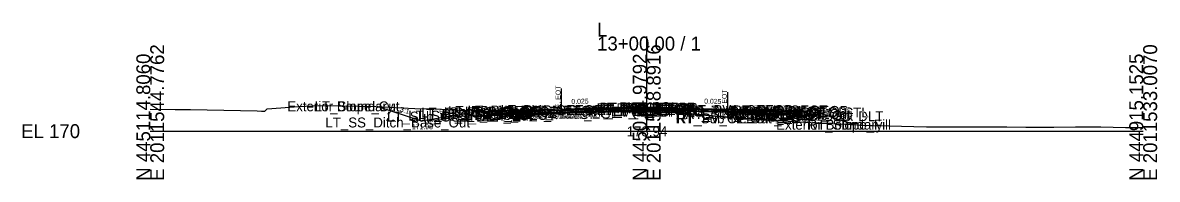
# Model space of a CAD drawing. Extents: x -26 to 4203, y -10 to 9526.
# Drawn here: x -25.7 to 202.8, y 2990.3 to 3021.8 of the extents above; entities that cross this region are included whole.
import ezdxf

# ---------------------------------------------------------------- set-up
doc = ezdxf.new("R2010")
doc.units = 0
for name, color, linetype in [('Default', 7, 'Continuous'), ('Exist CMT Pavement', 7, 'Continuous'), ('Exist Cross Section Cell', 7, 'Continuous'), ('Exist XS Center Line Elevation Label', 7, 'Continuous'), ('Exist XS Ground Line', 7, 'Continuous'), ('Prop CMT Pvmt Course 1', 7, 'Continuous'), ('Prop CMT Pvmt Course 1 Wedge', 7, 'Continuous'), ('Prop CMT Pvmt Course 2', 7, 'Continuous'), ('Prop CMT Pvmt Course 2 Wedge', 7, 'Continuous'), ('Prop CMT Pvmt Course 3', 7, 'Continuous'), ('Prop CMT Pvmt Course 3 Wedge', 7, 'Continuous'), ('Prop CMT Pvmt Surface', 7, 'Continuous'), ('Prop CMT Pvmt Surface Shoulder', 7, 'Continuous'), ('Prop CMT Pvmt Wedge Surface 1', 7, 'Continuous'), ('Prop CMT Pvmt Wedge Surface 2', 7, 'Continuous'), ('Prop CMT Pvmt Wedge Surface 3', 7, 'Continuous'), ('Prop CMT Shld Paved Course 1', 7, 'Continuous'), ('Prop CMT Shld Paved Course 2', 7, 'Continuous'), ('Prop CMT Shld Paved Course 3', 7, 'Continuous'), ('Prop CMT Slope Grass', 7, 'Continuous'), ('Prop CMT Subgrade Earthwork', 7, 'Continuous'), ('Prop XS Ditch Standard Text', 7, 'Continuous'), ('Prop XS Label Text', 7, 'Continuous'), ('Prop XS SE Text', 7, 'Continuous'), ('Prop XS Side Slope Text', 7, 'Continuous'), ('Scratch_Level_0', 7, 'Continuous')]:
    doc.layers.add(name, color=color, linetype=linetype)

msp = doc.modelspace()

# ---------------------------------------------------------------- linework, layer by layer
at = {"layer": 'Exist CMT Pavement'}
for points in [[(80.68, 3003.54), (81.66, 3003.57), (82.5, 3003.6), (82.74, 3003.61), (84.46, 3003.66), (84.88, 3003.67), (85.13, 3003.68), (87.41, 3003.75), (89.36, 3003.83), (89.86, 3003.85), (89.9, 3003.85), (92.24, 3003.89), (92.41, 3003.9), (92.53, 3003.9), (93.92, 3003.95), (94.77, 3003.96), (94.93, 3003.96), (96.98, 3003.96), (97.42, 3003.96), (99.36, 3003.95), (99.94, 3003.94), (100, 3003.94)], [(100, 3003.94), (100.59, 3003.91), (102.41, 3003.84), (104.06, 3003.77), (104.99, 3003.73), (105.05, 3003.73), (105.75, 3003.68), (107.43, 3003.55), (108.77, 3003.47), (109.9, 3003.39), (111.2, 3003.27), (112.43, 3003.15), (113.87, 3003.04), (114.93, 3002.96), (116.13, 3002.83), (116.24, 3002.82), (116.37, 3002.81), (117.45, 3002.67), (118.16, 3002.62), (118.55, 3002.57)]]:
    msp.add_lwpolyline(points, dxfattribs=at)
at = {"layer": 'Exist Cross Section Cell'}
for p, q in [((100, 3000), (100, 3019.03)), ((0, 3000), (100, 3000)), ((100, 3000), (200, 3000))]:
    msp.add_line(p, q, dxfattribs=at)
at = {"layer": 'Exist XS Ground Line'}
msp.add_lwpolyline([(0, 3004.45), (5.03, 3004.38), (8.14, 3004.34), (21.53, 3004.11), (22.4, 3004.05), (23.11, 3004.01), (23.53, 3004.51), (29.96, 3004.98), (33.94, 3005.14), (38.11, 3005.07), (45.41, 3004.96), (53.32, 3004.56), (57.33, 3004.49), (65.33, 3004.11), (65.98, 3004.11), (66.59, 3004.11), (67.2, 3004.09), (71.19, 3003.93), (76.37, 3003.67), (77.31, 3003.66), (78.95, 3003.6), (80.68, 3003.54), (81.66, 3003.57), (82.74, 3003.61), (84.46, 3003.66), (85.13, 3003.68), (87.41, 3003.75), (89.36, 3003.83), (89.9, 3003.85), (92.53, 3003.9), (93.92, 3003.95), (94.93, 3003.96), (96.98, 3003.96), (97.42, 3003.96), (99.36, 3003.95), (100, 3003.94), (100.59, 3003.91), (102.41, 3003.84), (104.06, 3003.77), (105.05, 3003.73), (105.75, 3003.68), (107.43, 3003.55), (108.77, 3003.47), (109.9, 3003.39), (111.2, 3003.27), (112.43, 3003.15), (113.87, 3003.04), (114.93, 3002.96), (116.24, 3002.82), (117.45, 3002.67), (118.16, 3002.62), (118.55, 3002.57), (125.06, 3002.24), (134.2, 3001.69), (134.8, 3001.65), (135.25, 3001.63), (135.81, 3001.6), (136.29, 3001.59), (144.77, 3001.15), (145.57, 3001.14), (148.75, 3001.07), (156.33, 3000.9), (163.07, 3000.85), (166.35, 3000.86), (172.53, 3000.84), (176.37, 3000.78), (181.99, 3000.83), (186.39, 3000.86), (191.45, 3000.88), (196.4, 3000.76), (200, 3000.72)], dxfattribs=at)
at = {"layer": 'Prop CMT Pvmt Course 1'}
for points in [[(100, 3004.83), (73.19, 3004.16)], [(73.19, 3004.16), (73.19, 3003.91)], [(73.19, 3003.91), (80.68, 3004.1)], [(82.74, 3004.28), (100, 3004.71)], [(82.74, 3004.15), (82.74, 3004.28)], [(100, 3004.58), (100, 3004.83)], [(100, 3004.83), (126.56, 3004.17)], [(100, 3004.58), (100, 3004.83)], [(100, 3004.71), (100, 3004.58), (100, 3004.58)], [(116.24, 3004.3), (100, 3004.71)], [(100, 3004.71), (100, 3004.58), (100, 3004.58)], [(116.24, 3004.18), (116.24, 3004.3)], [(126.56, 3003.92), (118.55, 3004.12)], [(126.56, 3004.17), (126.56, 3003.92)]]:
    msp.add_lwpolyline(points, dxfattribs=at)
at = {"layer": 'Prop CMT Pvmt Course 1 Wedge'}
for points in [[(82.74, 3004.28), (82.74, 3004.28), (84.46, 3004.32), (84.88, 3004.33), (85.13, 3004.34), (87.41, 3004.39), (89.36, 3004.44), (89.86, 3004.46), (89.9, 3004.46), (92.24, 3004.52), (92.41, 3004.52), (92.53, 3004.52), (93.92, 3004.56), (94.77, 3004.58), (94.93, 3004.58), (96.98, 3004.63), (97.42, 3004.64), (99.36, 3004.69), (99.94, 3004.71), (100, 3004.71)], [(100, 3004.58), (99.94, 3004.58), (99.36, 3004.57), (97.42, 3004.52), (96.98, 3004.51), (94.93, 3004.46), (94.77, 3004.45), (93.92, 3004.43), (92.53, 3004.4), (92.41, 3004.39), (92.24, 3004.39), (89.9, 3004.33), (89.86, 3004.33), (89.36, 3004.32), (87.41, 3004.27), (85.13, 3004.21), (84.88, 3004.21), (84.46, 3004.2), (82.74, 3004.15), (82.74, 3004.15)], [(82.74, 3004.15), (82.74, 3004.28)], [(100, 3004.58), (100, 3004.71)], [(100, 3004.71), (100, 3004.58)], [(100, 3004.71), (100.59, 3004.69), (102.41, 3004.65), (104.06, 3004.61), (104.99, 3004.58), (105.05, 3004.58), (105.75, 3004.57), (107.43, 3004.52), (108.77, 3004.49), (109.9, 3004.46), (111.2, 3004.43), (112.43, 3004.4), (113.87, 3004.36), (114.93, 3004.34), (116.13, 3004.31), (116.24, 3004.3)], [(116.24, 3004.18), (116.13, 3004.18), (114.93, 3004.21), (113.87, 3004.24), (112.43, 3004.27), (111.2, 3004.3), (109.9, 3004.34), (108.77, 3004.36), (107.43, 3004.4), (105.75, 3004.44), (105.05, 3004.46), (104.99, 3004.46), (104.06, 3004.48), (102.41, 3004.52), (100.59, 3004.57), (100, 3004.58)], [(116.24, 3004.3), (116.24, 3004.18)]]:
    msp.add_lwpolyline(points, dxfattribs=at)
at = {"layer": 'Prop CMT Pvmt Course 2'}
for points in [[(82.74, 3004.15), (73.19, 3003.91)], [(73.19, 3003.91), (73.19, 3003.58)], [(73.19, 3003.58), (80.68, 3003.77)], [(82.74, 3003.82), (82.74, 3004.15)], [(116.24, 3003.84), (116.24, 3004.18)], [(116.24, 3004.18), (126.56, 3003.92)], [(126.56, 3003.59), (118.55, 3003.79)], [(126.56, 3003.92), (126.56, 3003.59)]]:
    msp.add_lwpolyline(points, dxfattribs=at)
at = {"layer": 'Prop CMT Pvmt Course 2 Wedge'}
for points in [[(82.74, 3004.15), (82.74, 3004.15), (84.46, 3004.2), (84.88, 3004.21), (85.13, 3004.21), (87.41, 3004.27), (89.36, 3004.32), (89.86, 3004.33), (89.9, 3004.33), (92.24, 3004.39), (92.41, 3004.39), (92.53, 3004.4), (93.92, 3004.43), (94.77, 3004.45), (94.93, 3004.46), (96.98, 3004.51), (97.42, 3004.52), (99.36, 3004.57), (99.94, 3004.58), (100, 3004.58)], [(100, 3004.25), (99.94, 3004.25), (99.36, 3004.23), (97.42, 3004.19), (96.98, 3004.18), (94.93, 3004.12), (94.77, 3004.12), (93.92, 3004.1), (92.53, 3004.06), (92.41, 3004.06), (92.24, 3004.06), (89.9, 3004), (89.86, 3004), (89.36, 3003.98), (87.41, 3003.94), (85.13, 3003.88), (84.88, 3003.87), (84.46, 3003.86), (82.74, 3003.82), (82.74, 3003.82)], [(82.74, 3003.82), (82.74, 3004.15)], [(100, 3004.25), (100, 3004.58)], [(100, 3004.58), (100, 3004.25)], [(100, 3004.58), (100.59, 3004.57), (102.41, 3004.52), (104.06, 3004.48), (104.99, 3004.46), (105.05, 3004.46), (105.75, 3004.44), (107.43, 3004.4), (108.77, 3004.36), (109.9, 3004.34), (111.2, 3004.3), (112.43, 3004.27), (113.87, 3004.24), (114.93, 3004.21), (116.13, 3004.18), (116.24, 3004.18)], [(116.24, 3003.84), (116.13, 3003.85), (114.93, 3003.88), (113.87, 3003.9), (112.43, 3003.94), (111.2, 3003.97), (109.9, 3004), (108.77, 3004.03), (107.43, 3004.06), (105.75, 3004.11), (105.05, 3004.12), (104.99, 3004.13), (104.06, 3004.15), (102.41, 3004.19), (100.59, 3004.24), (100, 3004.25)], [(116.24, 3004.18), (116.24, 3003.84)]]:
    msp.add_lwpolyline(points, dxfattribs=at)
at = {"layer": 'Prop CMT Pvmt Course 3'}
for points in [[(82.74, 3003.82), (73.19, 3003.58)], [(73.19, 3003.58), (73.19, 3003.25)], [(73.19, 3003.25), (82.74, 3003.49)], [(82.74, 3003.49), (82.74, 3003.82)], [(116.24, 3003.84), (126.56, 3003.59)], [(116.24, 3003.51), (116.24, 3003.84)], [(126.56, 3003.25), (116.24, 3003.51)], [(126.56, 3003.59), (126.56, 3003.25)]]:
    msp.add_lwpolyline(points, dxfattribs=at)
at = {"layer": 'Prop CMT Pvmt Course 3 Wedge'}
for points in [[(100, 3003.94), (99.94, 3003.94), (99.36, 3003.95), (97.42, 3003.96), (96.98, 3003.96), (94.93, 3003.96), (94.77, 3003.96), (93.92, 3003.95), (92.53, 3003.9), (92.41, 3003.9), (92.24, 3003.89), (89.9, 3003.85), (89.86, 3003.85), (89.36, 3003.83), (87.41, 3003.75), (85.13, 3003.68), (84.88, 3003.67), (84.46, 3003.66), (82.74, 3003.61), (82.5, 3003.6), (81.66, 3003.57), (80.68, 3003.54)], [(82.74, 3003.82), (82.74, 3003.82), (84.46, 3003.86), (84.88, 3003.87), (85.13, 3003.88), (87.41, 3003.94), (89.36, 3003.98), (89.86, 3004), (89.9, 3004), (92.24, 3004.06), (92.41, 3004.06), (92.53, 3004.06), (93.92, 3004.1), (94.77, 3004.12), (94.93, 3004.12), (96.98, 3004.18), (97.42, 3004.19), (99.36, 3004.23), (99.94, 3004.25), (100, 3004.25)], [(82.74, 3003.59), (82.74, 3003.82)], [(100, 3003.94), (100, 3004.25)], [(100, 3004.25), (100, 3003.94)], [(100, 3004.25), (100.59, 3004.24), (102.41, 3004.19), (104.06, 3004.15), (104.99, 3004.13), (105.05, 3004.12), (105.75, 3004.11), (107.43, 3004.07), (108.77, 3004.03), (109.9, 3004), (111.2, 3003.97), (112.43, 3003.94), (113.87, 3003.9), (114.93, 3003.88), (116.13, 3003.85), (116.24, 3003.84)], [(118.55, 3002.57), (118.16, 3002.62), (117.45, 3002.67), (116.37, 3002.81), (116.24, 3002.82), (116.13, 3002.83), (114.93, 3002.96), (113.87, 3003.04), (112.43, 3003.15), (111.2, 3003.27), (109.9, 3003.39), (108.77, 3003.47), (107.43, 3003.55), (105.75, 3003.68), (105.05, 3003.73), (104.99, 3003.73), (104.06, 3003.77), (102.41, 3003.84), (100.59, 3003.91), (100, 3003.94)]]:
    msp.add_lwpolyline(points, dxfattribs=at)
at = {"layer": 'Prop CMT Pvmt Surface'}
for points in [[(100, 3004.83), (73.19, 3004.16)], [(100, 3004.83), (126.56, 3004.17)]]:
    msp.add_lwpolyline(points, dxfattribs=at)
at = {"layer": 'Prop CMT Pvmt Surface Shoulder'}
for points in [[(73.19, 3004.16), (69.19, 3004.06)], [(126.56, 3004.17), (130.57, 3004.07)]]:
    msp.add_lwpolyline(points, dxfattribs=at)
at = {"layer": 'Prop CMT Pvmt Wedge Surface 1'}
for points in [[(73.19, 3003.91), (73.19, 3004.16)], [(80.68, 3004.1), (73.19, 3003.91)], [(100, 3004.71), (82.74, 3004.28)], [(82.74, 3004.28), (82.74, 3004.15)], [(100, 3004.71), (116.24, 3004.3)], [(116.24, 3004.3), (116.24, 3004.18)], [(118.55, 3004.12), (126.56, 3003.92)], [(126.56, 3003.92), (126.56, 3004.17)]]:
    msp.add_lwpolyline(points, dxfattribs=at)
at = {"layer": 'Prop CMT Pvmt Wedge Surface 2'}
for points in [[(73.19, 3003.91), (73.19, 3004.16)], [(100, 3004.58), (82.74, 3004.15)], [(100, 3004.58), (116.24, 3004.18)], [(126.56, 3003.92), (126.56, 3004.17)]]:
    msp.add_lwpolyline(points, dxfattribs=at)
at = {"layer": 'Prop CMT Pvmt Wedge Surface 3'}
for points in [[(73.19, 3003.58), (73.19, 3004.16)], [(100, 3004.25), (82.74, 3003.82)], [(100, 3004.25), (116.24, 3003.85)], [(126.56, 3003.59), (126.56, 3004.17)]]:
    msp.add_lwpolyline(points, dxfattribs=at)
at = {"layer": 'Prop CMT Shld Paved Course 1'}
for points in [[(73.19, 3004.16), (69.19, 3004.06), (68.94, 3003.81)], [(68.94, 3003.81), (73.19, 3003.91)], [(73.19, 3003.91), (73.19, 3004.16)], [(126.56, 3004.17), (130.57, 3004.07), (130.82, 3003.81)], [(126.56, 3003.92), (126.56, 3004.17)], [(130.82, 3003.81), (126.56, 3003.92)]]:
    msp.add_lwpolyline(points, dxfattribs=at)
at = {"layer": 'Prop CMT Shld Paved Course 2'}
for points in [[(73.19, 3003.91), (68.94, 3003.81), (68.59, 3003.47)], [(68.59, 3003.47), (73.19, 3003.58)], [(73.19, 3003.58), (73.19, 3003.91)], [(126.56, 3003.92), (130.82, 3003.81), (131.17, 3003.47)], [(126.56, 3003.59), (126.56, 3003.92)], [(131.17, 3003.47), (126.56, 3003.59)]]:
    msp.add_lwpolyline(points, dxfattribs=at)
at = {"layer": 'Prop CMT Shld Paved Course 3'}
for points in [[(73.19, 3003.58), (69.09, 3003.48), (68.59, 3003.47), (68.25, 3003.12)], [(68.25, 3003.12), (73.19, 3003.25)], [(73.19, 3003.25), (73.19, 3003.58)], [(126.56, 3003.59), (130.66, 3003.48), (131.17, 3003.47), (131.51, 3003.13)], [(126.56, 3003.25), (126.56, 3003.59)], [(131.51, 3003.13), (126.56, 3003.25)]]:
    msp.add_lwpolyline(points, dxfattribs=at)
at = {"layer": 'Prop CMT Slope Grass'}
for points in [[(69.19, 3004.06), (65.19, 3003.74), (54.61, 3001.98), (45.73, 3004.94)], [(130.57, 3004.07), (134.56, 3003.75), (141.93, 3001.3)]]:
    msp.add_lwpolyline(points, dxfattribs=at)
at = {"layer": 'Prop CMT Subgrade Earthwork'}
for points in [[(67.75, 3003.11), (60.28, 3002.93)], [(73.19, 3003.25), (67.75, 3003.11)], [(82.74, 3003.49), (73.19, 3003.25)], [(82.74, 3003.49), (82.74, 3003.61)], [(116.24, 3003.51), (126.56, 3003.25)], [(116.24, 3003.51), (116.24, 3002.82)], [(126.56, 3003.25), (132.01, 3003.12)], [(132.01, 3003.12), (136.82, 3003)]]:
    msp.add_lwpolyline(points, dxfattribs=at)
at = {"layer": 'Prop XS Label Text'}
for p, q in [((82.74, 3008.61), (82.74, 3003.61)), ((116.24, 3007.82), (116.24, 3002.82))]:
    msp.add_line(p, q, dxfattribs=at)

# ---------------------------------------------------------------- texts
at = {"layer": 'Default'}
msp.add_text('-', height=0.0001, dxfattribs=at).set_placement((0, 3000))
at = {"layer": 'Exist Cross Section Cell'}
for s, p in [('L', (90, 3019.03)), ('13+00.00 / 1', (90, 3016.23)), ('EL 170', (-26, 2998.6))]:
    msp.add_text(s, height=2.8, dxfattribs=at).set_placement(p)
for s, p in [('E 2011544.7762', (2.8, 2990)), ('E 2011538.8916', (102.8, 2990)), ('E 2011533.0070', (202.8, 2990)), ('N 445114.8060', (0, 2990)), ('N 445014.9792', (100, 2990)), ('N 444915.1525', (200, 2990))]:
    msp.add_text(s, height=2.8, rotation=90, dxfattribs=at).set_placement(p)
at = {"layer": 'Exist XS Center Line Elevation Label'}
msp.add_text('173.94', height=2, dxfattribs=at).set_placement((95.96, 2998.94))
at = {"layer": 'Prop XS Ditch Standard Text'}
msp.add_text('171.98', height=1, dxfattribs=at).set_placement((52.71, 3000.39))
at = {"layer": 'Prop XS Label Text'}
for p in [(82.64, 3004.63), (116.14, 3003.85)]:
    msp.add_text('E. EOT', height=1, rotation=90, dxfattribs=at).set_placement(p)
at = {"layer": 'Prop XS SE Text'}
for rotation, p in [(1.4318, (84.84, 3005.46)), (358.5681, (111.57, 3005.55))]:
    msp.add_text('0.025', height=1, rotation=rotation, dxfattribs=at).set_placement(p)
at = {"layer": 'Prop XS Side Slope Text'}
for s, rotation, p in [('3:1', 341.5613, (50.21, 3004.02)), ('6:1', 9.4625, (58.29, 3003.35)), ('3:1', 341.5717, (137.73, 3003.49))]:
    msp.add_text(s, height=1, rotation=rotation, dxfattribs=at).set_placement(p)
at = {"layer": 'Scratch_Level_0'}
for s, p in [('Exterior Boundary', (27.61, 3003.99)), ('LT_Slope_Cut', (33.1, 3003.99)), ('LT_PV1_OEEOP', (70.55, 3003.23)), ('RT_PV2_IEEOP', (89.91, 3003.58)), ('RT_PV3_IEEOP', (89.91, 3003.25)), ('LT_PV2_IEEOP', (89.95, 3003.58)), ('LT_PV3_IEEOP', (89.95, 3003.25)), ('RT_PV1_IEEOP', (90.47, 3003.71)), ('LT_PV1_IEEOP', (90.52, 3003.71)), ('PV2_PGL', (93.91, 3003.58)), ('PV1_PGL', (94.47, 3003.83)), ('RT_PV1_OEEOP', (108.38, 3003.24)), ('LT_Sub_OSS_DLT', (47.68, 3001.93)), ('LT_Sub_Trench_Out', (51.96, 3002.11)), ('LT_PS3_Shelf_Out', (54.08, 3002.45)), ('LT_GS_OS_CTL', (54.57, 3002.74)), ('LT_PS3_OEOP', (58.83, 3002.47)), ('LT_PS2_OEOP', (59.17, 3002.81)), ('LT_PS1_OEOP', (60, 3003.06)), ('LT_Sub_OEOT', (63.27, 3002.25)), ('LT_PV2_OEOT', (63.37, 3002.91)), ('LT_PV3_OEOT', (63.37, 3002.58)), ('LT_PV1_OEOT', (63.94, 3003.16)), ('LT_Sub Tie Out', (68.02, 3002.54)), ('LT_PV_OEEOP_EG', (68.22, 3002.54)), ('LT_Sub_OEEOP', (69.89, 3002.43)), ('LT_PV2_OEEOP', (69.98, 3003.1)), ('LT_PV3_OEEOP', (69.98, 3002.77)), ('RT_PV_IEEOP_EG', (88.14, 3002.94)), ('LT_PV_IEEOP_EG', (88.19, 3002.94)), ('RT_Sub Tie Out', (105.84, 3001.57)), ('RT_PV_OEEOP_EG', (106.05, 3001.57)), ('RT_Sub_OEEOP', (107.72, 3002.45)), ('RT_PV2_OEEOP', (107.81, 3003.12)), ('RT_PV3_OEEOP', (107.81, 3002.79)), ('RT_Sub_Trench_Out', (116.17, 3002.12)), ('RT_Sub_OEOT', (116.6, 3002.25)), ('RT_PV2_OEOT', (116.69, 3002.92)), ('RT_PV3_OEOT', (116.69, 3002.59)), ('RT_PV1_OEOT', (117.26, 3003.17)), ('RT_PS3_Shelf_Out', (117.6, 3002.46)), ('RT_PS2_OEOP', (121.01, 3002.81)), ('RT_PS1_OEOP', (121.32, 3003.07)), ('RT_PS3_OEOP', (121.35, 3002.47)), ('RT_GS_OS_CTL', (123.89, 3002.75)), ('RT_Sub_OSS_DLT', (124.18, 3002)), ('LT_SS_Ditch_Base_Out', (35.27, 3000.74)), ('Exterior Boundary', (126.07, 3000.3)), ('RT_Slope_Fill', (132.4, 3000.3))]:
    msp.add_text(s, height=2, dxfattribs=at).set_placement(p)

doc.saveas('drawing.dxf')
